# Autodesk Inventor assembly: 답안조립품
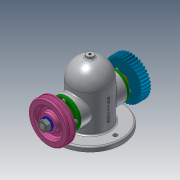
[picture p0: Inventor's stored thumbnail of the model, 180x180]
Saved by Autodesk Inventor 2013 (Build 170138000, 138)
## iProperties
Created: 2019-11
Part Number: 답안조립품
Document SubType Name: Assembly
Designer: user
Author: user
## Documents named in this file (14)
- C:\Users\user\Desktop\491104V1043\답안조립품.iam
- C:\Users\user\Desktop\491104V1043\본체.ipt
- C:\Users\user\Desktop\491104V1043\V-벨트풀리.ipt
- V-벨트풀리.ipt
- C:\Users\user\Desktop\491104V1043\너트 M12x1.25.ipt
- C:\Users\user\Desktop\491104V1043\베어링 6203.ipt
- C:\Users\user\Desktop\491104V1043\볼트 M4.ipt
- C:\Users\user\Desktop\491104V1043\부시.ipt
- C:\Users\user\Desktop\491104V1043\스퍼기어.ipt
- C:\Users\user\Desktop\491104V1043\오일 실 26 38 8.ipt
- C:\Users\user\Desktop\491104V1043\와셔 12x24.ipt
- C:\Users\user\Desktop\491104V1043\축.ipt
- C:\Users\user\Desktop\491104V1043\커버.ipt
- C:\Users\user\Desktop\491104V1043\키 5x5x12.ipt
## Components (1 placed, 1 different names)
1. V-벨트풀리:1
